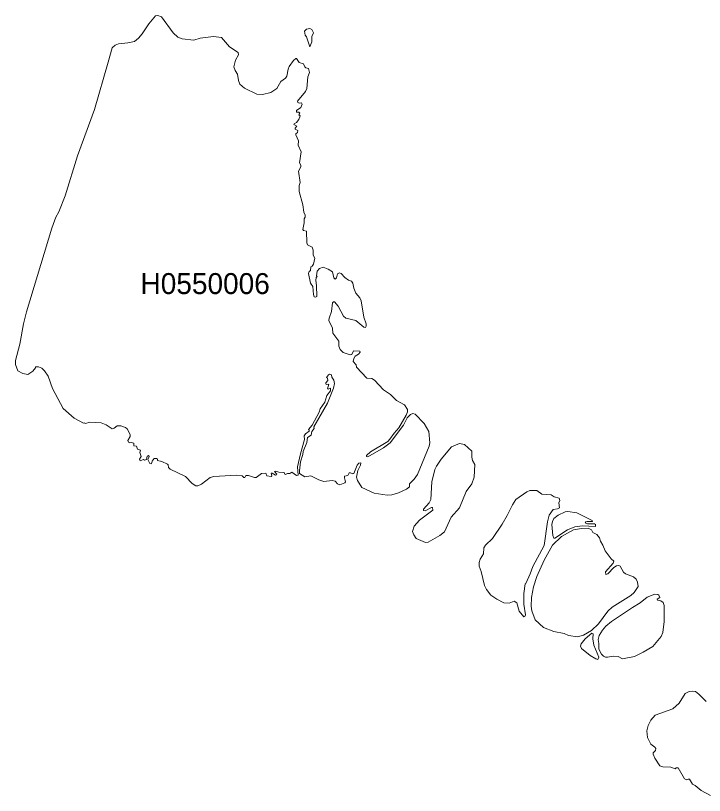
# Model space of a CAD drawing. Extents: x 369010 to 739155, y 6377141 to 6616555.
# Drawn here: x 442416 to 445703, y 6497433 to 6501156 of the extents above; entities that cross this region are included whole.
import ezdxf
from ezdxf.enums import TextEntityAlignment as Align

# ---------------------------------------------------------------- set-up
doc = ezdxf.new("R2010")
doc.units = 0
doc.header["$LTSCALE"] = 40
doc.layers.add('1', color=7, linetype='Continuous', lineweight=13)
doc.layers.add('2', color=7, linetype='Continuous')

msp = doc.modelspace()

# ---------------------------------------------------------------- linework, layer by layer
at = {"layer": '1'}
for points in [[(443743.87, 6500635.6), (443744.86, 6500639.24), (443756.45, 6500645.37), (443767.53, 6500660.26), (443773, 6500677.64), (443768.03, 6500681.61), (443771.67, 6500690.05), (443766.87, 6500695.68), (443755.62, 6500695.51), (443756.45, 6500702.8), (443777.13, 6500718.02), (443782.76, 6500733.58), (443779.45, 6500739.04), (443769.52, 6500738.05), (443762.07, 6500741.03), (443760.42, 6500746.82), (443799.48, 6500793.66), (443805.27, 6500807.89), (443809.9, 6500863.5), (443817.52, 6500885.02), (443813.71, 6500903.88), (443801.13, 6500906.37), (443795.34, 6500911.17), (443789.22, 6500926.06), (443769.52, 6500931.52), (443756.45, 6500951.05), (443753.3, 6500951.05), (443742.38, 6500942.28), (443721.69, 6500913.81), (443716.06, 6500899.58), (443710.6, 6500866.98), (443703.48, 6500856.72), (443681.8, 6500842.15), (443662.11, 6500807.56), (443633.81, 6500789.69), (443594.25, 6500778.76), (443566.61, 6500780.42), (443508.69, 6500809.71), (443485.68, 6500828.91), (443479.23, 6500845.96), (443474.76, 6500875.75), (443462.84, 6500893.79), (443457.71, 6500912.16), (443464.5, 6500943.61), (443479.56, 6500969.09), (443478.07, 6500979.35), (443436.36, 6501007.16), (443398.13, 6501052.18), (443359.57, 6501055.98), (443297.01, 6501048.53), (443266.72, 6501039.6), (443210.61, 6501044.89), (443190.59, 6501052.34), (443167.09, 6501074.02), (443111.31, 6501150.32), (443095.09, 6501156.11), (443083.51, 6501154.79), (443051.73, 6501116.72), (443020.12, 6501069.55), (443001.75, 6501048.2), (442982.38, 6501032.15), (442951.93, 6501025.36), (442906.75, 6501021.72), (442891.19, 6501014.94), (442876.63, 6501001.7), (442857.26, 6500933.18), (442792.39, 6500708.26), (442710.63, 6500487.31), (442651.87, 6500295.33), (442621.42, 6500219.86), (442607.85, 6500193.87), (442588.82, 6500141.57), (442467.34, 6499742.21), (442453.43, 6499684.12), (442436.22, 6499587.13), (442415.53, 6499509.51), (442415.53, 6499490.15), (442426.62, 6499460.52), (442450.45, 6499447.61), (442473.79, 6499442.98), (442498.28, 6499458.87), (442510.86, 6499474.1)], [(444040.29, 6499489.16), (444026.38, 6499504.38), (444029.2, 6499518.62), (444036.31, 6499529.87), (444051.54, 6499539.3), (444059.32, 6499549.73), (444058.66, 6499554.2), (444028.2, 6499555.19), (444019.93, 6499537.98), (444011.82, 6499536.16), (443978.55, 6499548.41), (443963.99, 6499562.31), (443958.2, 6499578.03), (443957.86, 6499602.36), (443929.73, 6499640.76), (443928.74, 6499664.09), (443911.03, 6499700.5), (443911.69, 6499711.92), (443922.94, 6499742.87), (443927.41, 6499784.91), (443932.05, 6499789.71), (443937.84, 6499790.04), (443954.55, 6499768.69), (443980.04, 6499721.85), (443991.46, 6499710.93), (444038.63, 6499701.17), (444077.69, 6499668.56), (444086.13, 6499667.24), (444089.27, 6499673.69), (444088.61, 6499685.28), (444078.02, 6499716.39), (444064.12, 6499793.85), (444058.66, 6499809.41), (444039.29, 6499831.42), (444029.2, 6499854.59), (444025.06, 6499877.92), (444018.6, 6499888.02), (444004.7, 6499892.82), (443986.5, 6499905.4), (443968.79, 6499925.42), (443962, 6499927.74), (443951.08, 6499923.44), (443947.44, 6499904.9), (443940.16, 6499897.62), (443933.7, 6499904.07), (443927.74, 6499932.87), (443907.05, 6499945.78), (443883.22, 6499954.88), (443865.68, 6499949.42), (443854.09, 6499936.68), (443852.11, 6499914.5), (443854.42, 6499910.53), (443849.29, 6499906.39), (443847.97, 6499890.83), (443851.78, 6499867.66), (443853.1, 6499815.53), (443847.31, 6499811.39), (443841.18, 6499814.04), (443837.05, 6499824.96), (443833.41, 6499862.04), (443823.47, 6499878.59), (443813.38, 6499924.43), (443816.36, 6499934.2), (443822.48, 6499939.33), (443823.97, 6499956.04), (443831.42, 6499959.35), (443836.72, 6499969.12), (443843.17, 6499998.08), (443836.05, 6500012.98), (443835.39, 6500035.65), (443830.76, 6500049.88), (443808.91, 6500062.46), (443805.6, 6500071.07), (443803.12, 6500127.67), (443788.88, 6500130.32), (443786.57, 6500134.46), (443793.02, 6500167.39), (443793.02, 6500185.27), (443797.16, 6500193.21), (443797.16, 6500202.97), (443791.37, 6500217.21), (443786.57, 6500252.79), (443769.52, 6500316.68), (443768.53, 6500345.14), (443773, 6500359.38), (443765.55, 6500413.66), (443777.46, 6500433.69), (443776.8, 6500442.13), (443769.69, 6500453.71), (443779.12, 6500505.35), (443764.56, 6500537.13), (443765.22, 6500558.48), (443752.97, 6500586.12), (443753.3, 6500592.41), (443760.75, 6500597.54), (443762.07, 6500607.47), (443749.99, 6500614.58), (443749.16, 6500618.56), (443757.44, 6500628.49), (443743.87, 6500635.6)], [(443830.26, 6499201.34), (443864.69, 6499263.41), (443869.65, 6499278.8), (443890.67, 6499309.92), (443900.27, 6499343.18), (443918.47, 6499364.86), (443918.47, 6499378.1), (443906.72, 6499372.64), (443904.24, 6499374.13), (443910.03, 6499397.14), (443897.79, 6499394.82), (443895.47, 6499397.47), (443896.13, 6499402.93), (443905.73, 6499414.51), (443904.9, 6499424.61), (443899.11, 6499427.59), (443908.38, 6499441.66), (443913.84, 6499443.64), (443922.94, 6499440.83), (443924.27, 6499430.07), (443934.53, 6499416.17), (443936.85, 6499399.12), (443932.05, 6499377.77), (443904.57, 6499306.61), (443838.87, 6499192.24), (443841.18, 6499184.79), (443829.27, 6499171.22), (443825.96, 6499153.84), (443808.25, 6499141.6), (443805.93, 6499117.93), (443788.22, 6499075.4), (443786.9, 6499061.16), (443775.64, 6499025.58), (443769.69, 6498982.88), (443770.68, 6498970.63), (443796, 6498954.41), (443824.3, 6498958.38), (443863.2, 6498939.35), (443886.7, 6498931.24), (443927.08, 6498936.04), (443941.31, 6498933.39), (443951.41, 6498921.15), (443963.66, 6498915.35), (443986.83, 6498925.78), (443990.8, 6498930.91), (443985.34, 6498949.28), (443986, 6498957.72), (444001.06, 6498960.7), (444008.18, 6498972.62), (444014.63, 6498973.61), (444025.22, 6498968.31), (444030.52, 6498969.64), (444045.08, 6499009.69), (444053.19, 6499019.79), (444062.79, 6499020.78), (444061.14, 6499010.35), (444048.23, 6498984.87), (444041.77, 6498953.25), (444046.74, 6498936.37), (444068.26, 6498903.11), (444126.18, 6498875.63), (444188.25, 6498867.19), (444211.42, 6498867.52), (444242.53, 6498877.29), (444281.26, 6498895.33), (444295.16, 6498906.09), (444294.83, 6498921.48), (444317.5, 6498943.16), (444332.9, 6498965.5), (444389.5, 6499099.89), (444392.81, 6499116.61), (444388.17, 6499170.89), (444365.5, 6499208.13), (444322.63, 6499253.64), (444310.72, 6499256.95), (444300.62, 6499251.99), (444283.58, 6499235.6), (444267.36, 6499201.01), (444202.48, 6499116.94), (444170.7, 6499092.44), (444096.72, 6499050.07), (444090.6, 6499051.73), (444090.27, 6499055.87), (444108.64, 6499072.75), (444191.72, 6499122.9), (444202.15, 6499133.49), (444221.84, 6499162.62), (444244.02, 6499188.44), (444279.6, 6499248.51), (444286.06, 6499264.07), (444286.72, 6499276.32), (444272.16, 6499297.34), (444234.09, 6499318.36), (444204.3, 6499346.66), (444171.7, 6499369.33), (444128.66, 6499415.51), (444115.75, 6499423.62), (444091.92, 6499425.27), (444041.77, 6499477.24), (444040.29, 6499489.16)], [(442510.86, 6499474.1), (442510.86, 6499479.23), (442524.1, 6499478.89), (442540.32, 6499472.77), (442553.23, 6499460.19), (442570.78, 6499435.2), (442591.96, 6499375.12), (442643.1, 6499280.12), (442695.4, 6499234.28), (442740.09, 6499210.45), (442742.9, 6499211.94), (442749.02, 6499208.46), (442769.05, 6499214.58), (442824, 6499212.27), (442848.33, 6499202.34), (442876.3, 6499183.97), (442886.06, 6499185.79), (442899.8, 6499197.04), (442918.17, 6499197.54), (442939.68, 6499189.43), (442948.46, 6499182.64), (442963.02, 6499156.99), (442962.69, 6499146.73), (442951.27, 6499128.03), (442954.58, 6499120.25), (442961.03, 6499116.61), (442967.49, 6499118.59), (442980.07, 6499115.45), (442980.07, 6499102.7), (442992.98, 6499100.88), (442997.61, 6499085.66), (443011.35, 6499080.86), (443007.87, 6499070.1), (443015.32, 6499050.74), (443007.21, 6499038.49), (443010.19, 6499031.04), (443026.57, 6499037.16), (443030.88, 6499033.69), (443040.97, 6499036.5), (443043.45, 6499053.05), (443049.41, 6499056.53), (443052.56, 6499051.07), (443047.1, 6499037.66), (443056.2, 6499017.14), (443063.81, 6499015.81), (443067.29, 6499029.72), (443077.05, 6499041.47), (443087.31, 6499041.47), (443092.28, 6499038.49), (443092.77, 6499031.7), (443113.46, 6499027.9), (443139.78, 6499015.15), (443143.25, 6499011.68), (443145.9, 6498999.1), (443153.35, 6498990.99), (443225.67, 6498955.07), (443257.95, 6498922.8), (443275.66, 6498911.55), (443284.76, 6498911.88), (443302.8, 6498918.99), (443343.51, 6498950.27), (443361.72, 6498955.41), (443470.29, 6498962.85), (443497.1, 6498959.38), (443505.54, 6498951.27), (443510.01, 6498951.6), (443515.14, 6498960.04), (443527.06, 6498960.7), (443555.85, 6498950.27), (443563.96, 6498950.94), (443588.46, 6498970.3), (443610.14, 6498970.96), (443614.28, 6498959.05), (443635.3, 6498956.4), (443637.94, 6498958.38), (443635.96, 6498972.29), (443640.76, 6498972.29), (443656.32, 6498962.85), (443660.95, 6498963.85), (443662.77, 6498967.32), (443651.52, 6498980.07), (443658.3, 6498981.22), (443671.54, 6498976.76), (443696.53, 6498975.43), (443700.01, 6498966.16), (443703.48, 6498965.83), (443712.92, 6498970.63), (443724.83, 6498970.3), (443734.6, 6498977.09), (443755.95, 6498961.2), (443764.89, 6498961.53), (443760.75, 6499002.24), (443774.65, 6499064.31), (443795.01, 6499133.16), (443792.03, 6499150.53), (443798.48, 6499159.64), (443816.36, 6499172.88), (443817.19, 6499177.35), (443814.04, 6499180.66), (443830.26, 6499201.34)], [(445711.05, 6497880.79), (445676.46, 6497916.37), (445660.57, 6497928.62), (445646, 6497930.94), (445630.28, 6497929.28), (445610.59, 6497919.52), (445581.79, 6497874), (445552.99, 6497845.87), (445468.75, 6497815.58), (445446.74, 6497793.24), (445434.16, 6497767.42), (445428.7, 6497741.43), (445431.84, 6497709.16), (445447.07, 6497677.55), (445466.76, 6497663.98), (445471.23, 6497657.52), (445469.91, 6497648.42), (445457.99, 6497636.84), (445458.65, 6497629.72), (445466.76, 6497610.35), (445489.77, 6497574.77), (445504.5, 6497570.3), (445543.39, 6497567.99), (445563.09, 6497559.54), (445567.89, 6497564.18), (445577.32, 6497564.18), (445607.94, 6497512.71), (445619.52, 6497507.58), (445625.65, 6497511.38), (445632.1, 6497510.56), (445646, 6497486.89), (445659.25, 6497480.43), (445687.05, 6497455.94), (445731.4, 6497433.27)]]:
    msp.add_lwpolyline(points, dxfattribs=at)
for points in [[(443819.5, 6501006.99), (443828.77, 6501030.66), (443829.93, 6501055.65), (443836.55, 6501073.19), (443829.93, 6501089.58), (443820.16, 6501093.88), (443803.12, 6501091.57), (443794.02, 6501082.3), (443797.66, 6501062.27), (443803.78, 6501054.33)], [(444558.15, 6499108.66), (444534.65, 6499113.13), (444495.75, 6499096.58), (444446.43, 6499039.15), (444424.09, 6499005.55), (444415.98, 6498988.67), (444402.08, 6498929.92), (444396.62, 6498845.84), (444389.5, 6498830.12), (444362.36, 6498799), (444363.02, 6498793.54), (444370.47, 6498792.22), (444400.09, 6498808.11), (444405.72, 6498807.78), (444407.54, 6498794.87), (444343.98, 6498747.04), (444317.5, 6498718.57), (444310.39, 6498693.41), (444316.18, 6498676.53), (444326.77, 6498659.48), (444371.13, 6498641.11), (444384.7, 6498642.11), (444439.98, 6498673.72), (444461.82, 6498691.43), (444493.6, 6498761.93), (444533.32, 6498805.79), (444565.59, 6498884.07), (444593.73, 6498920.48), (444603.33, 6498951.93), (444607.63, 6499013.66), (444596.21, 6499032.7), (444592.41, 6499047.92), (444592.74, 6499075.89)], [(444903.55, 6498888.21), (444869.96, 6498889.53), (444855.72, 6498883.08), (444803.76, 6498845.18), (444786.54, 6498820.02), (444762.05, 6498769.71), (444737.22, 6498727.67), (444691.87, 6498660.48), (444657.95, 6498628.7), (444649.67, 6498615.79), (444649.01, 6498586.83), (444633.45, 6498561.51), (444627.33, 6498544.79), (444627.99, 6498527.91), (444638.25, 6498502.75), (444654.14, 6498435.56), (444663.24, 6498416.19), (444684.43, 6498389.71), (444712.23, 6498369.69), (444745.17, 6498352.81), (444770.49, 6498350.82), (444795.65, 6498360.25), (444808.22, 6498352.14), (444818.98, 6498313.42), (444840.5, 6498285.94), (444845.13, 6498286.93), (444849.27, 6498296.04), (444841.16, 6498346.35), (444841.49, 6498396.83), (444847.61, 6498442.67), (444851.25, 6498444.66), (444871.94, 6498490.5), (444884.19, 6498526.09), (444937.48, 6498625.56), (444953.7, 6498739.26), (444962.64, 6498770.37), (444981.18, 6498798.34), (445002.36, 6498801.32), (445011.13, 6498806.45), (445008.98, 6498830.45), (445012.46, 6498841.7), (445009.48, 6498852.13), (444985.31, 6498858.92), (444971.41, 6498868.85), (444927.55, 6498871.83)], [(445093.55, 6498782.95), (445051.51, 6498788.41), (445037.94, 6498786.76), (445004.68, 6498771.86), (444984.98, 6498754.48), (444977.87, 6498740.58), (444975.55, 6498726.35), (444979.52, 6498673.39), (444984.98, 6498661.8), (444989.45, 6498660.81), (445049.03, 6498701.52), (445084.45, 6498715.09), (445120.03, 6498719.56), (445183.42, 6498717.58), (445183.42, 6498726.02), (445178.29, 6498729), (445144.69, 6498729.66), (445133.94, 6498734.46), (445136.42, 6498740.08), (445142.71, 6498741.57), (445169.19, 6498741.24), (445167.86, 6498745.38)], [(445241.84, 6498312.09), (445262.2, 6498332.12), (445352.07, 6498387.73), (445368.12, 6498402.29), (445386.33, 6498430.1), (445384.01, 6498451.78), (445376.56, 6498466.01), (445363.99, 6498476.6), (445325.92, 6498490.5), (445316.16, 6498499.28), (445300.93, 6498527.91), (445294.81, 6498531.55), (445282.89, 6498528.9), (445270.64, 6498520.79), (445242.51, 6498490.84), (445232.24, 6498487.19), (445231.25, 6498500.77), (445267.99, 6498542.14), (445270.64, 6498551.91), (445258.39, 6498562.17), (445228.93, 6498600.4), (445218.34, 6498628.7), (445206.26, 6498646.24), (445202.79, 6498663.29), (445189.21, 6498678.52), (445170.84, 6498688.28), (445164.06, 6498700.53), (445148.5, 6498708.97), (445116.89, 6498707.65), (445078, 6498700.86), (445020.9, 6498668.92), (444977.87, 6498628.54), (444938.48, 6498557.04), (444903.22, 6498478.26), (444886.51, 6498428.44), (444877.4, 6498378.62), (444876.08, 6498336.09), (444879.06, 6498314.74), (444895.78, 6498271.71), (444934.5, 6498234.3), (444983.66, 6498216.43), (445033.47, 6498205.84), (445054.82, 6498196.74), (445097.36, 6498190.94), (445125.83, 6498198.39), (445164.39, 6498220.4), (445196.99, 6498252.68)], [(445360.01, 6498330.96), (445259.06, 6498264.26), (445232.24, 6498241.09), (445216.03, 6498222.22), (445201.46, 6498196.4), (445195.67, 6498177.04), (445199.14, 6498157.68), (445198.81, 6498131.86), (445211.23, 6498107.86), (445222.15, 6498097.93), (445231.58, 6498093.13), (445240.85, 6498092.47), (445269.32, 6498097.27), (445290.67, 6498095.94), (445312.68, 6498086.01), (445369.45, 6498095.94), (445411.15, 6498116.3), (445456.17, 6498144.77), (445496.72, 6498191.94), (445504.83, 6498211.3), (445510.29, 6498263.1), (445510.13, 6498340.56), (445506.82, 6498353.47), (445495.56, 6498362.24), (445478.35, 6498364.72), (445477.03, 6498369.69), (445489.77, 6498378.62), (445485.8, 6498388.72), (445480.67, 6498392.2), (445466.43, 6498394.18), (445429.03, 6498380.28), (445396.26, 6498352.14)], [(445170.51, 6498180.35), (445171.5, 6498204.18), (445165.22, 6498207.82), (445134.27, 6498181.01), (445115.56, 6498157.01), (445111.26, 6498146.09), (445116.56, 6498133.84), (445157.6, 6498100.74), (445184.75, 6498084.69), (445194.68, 6498082.7), (445198.32, 6498093.46), (445174.65, 6498151.22)]]:
    msp.add_lwpolyline(points, close=True, dxfattribs=at)

# ---------------------------------------------------------------- texts
at = {"layer": '2'}
msp.add_text('H0550006', height=100, dxfattribs=at).set_placement((443320.21, 6499826.7), align=Align.CENTER)

doc.saveas('drawing.dxf')
